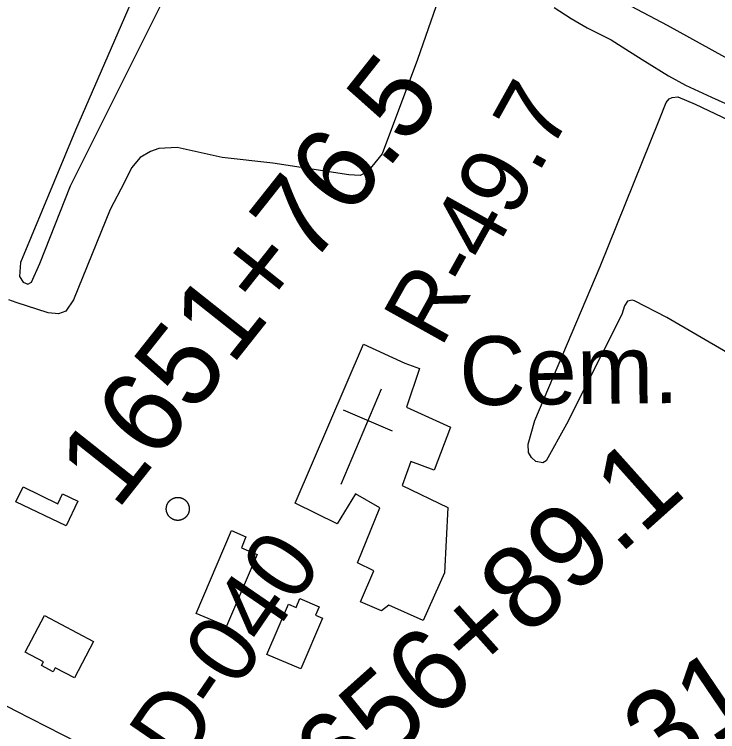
# Model space of a CAD drawing. Extents: x 3734862 to 3772949, y 391520 to 417239.
# Drawn here: x 3765922 to 3766771, y 398025 to 398891 of the extents above; entities that cross this region are included whole.
import ezdxf

# ---------------------------------------------------------------- set-up
doc = ezdxf.new("R2010")
doc.units = 0
for name, color, linetype in [('V-BLDG-IDEN', 7, 'Continuous'), ('V-BLDG-OTLN', 7, 'Continuous'), ('V-DOMW-TANK', 7, 'Continuous'), ('V-RIVR-EDGE', 7, 'Continuous'), ('V-RIVR-RANG-IDEN', 7, 'Continuous'), ('V-ROAD-CNTR', 7, 'Continuous'), ('V-SITE-OTLN', 7, 'Continuous'), ('V-SITE-VEGE', 7, 'Continuous'), ('V-SURV-IDEN', 7, 'Continuous'), ('V-TOPO-SHOR', 7, 'Continuous')]:
    doc.layers.add(name, color=color, linetype=linetype)

msp = doc.modelspace()

# ---------------------------------------------------------------- linework, layer by layer
at = {"layer": 'V-BLDG-OTLN'}
for points in [[(3765984.11, 398273.48), (3765923.61, 398302.47), (3765932.15, 398320.29), (3765974.36, 398300.06), (3765979.97, 398311.78), (3765998.26, 398303.01)], [(3766214.75, 398238.73), (3766178.08, 398152.14), (3766141.41, 398167.66), (3766183.75, 398267.61), (3766201.41, 398260.13), (3766195.8, 398246.75)], [(3766293.67, 398161.73), (3766267.64, 398100.65), (3766226.78, 398118.05), (3766252.6, 398178.65), (3766261.95, 398174.67), (3766266.6, 398185.57), (3766289.69, 398175.72), (3766285.26, 398165.31)], [(3765958.12, 398164.97), (3766017.44, 398133.6), (3765994.21, 398089.68), (3765970.89, 398102.02), (3765968.35, 398097.21), (3765954.39, 398104.59), (3765956.89, 398109.32), (3765934.86, 398120.97)]]:
    msp.add_lwpolyline(points, close=True, dxfattribs=at)
at = {"layer": 'V-DOMW-TANK'}
for points in [[(3766108.56, 398302.86), (3766108.72, 398303.04), (3766108.88, 398303.22), (3766109.05, 398303.4), (3766109.22, 398303.57), (3766109.39, 398303.74), (3766109.56, 398303.91), (3766109.74, 398304.07), (3766109.93, 398304.23), (3766110.11, 398304.39), (3766110.3, 398304.54), (3766110.48, 398304.7), (3766110.68, 398304.84), (3766110.87, 398304.99), (3766111.07, 398305.13), (3766111.27, 398305.26), (3766111.47, 398305.4), (3766111.67, 398305.53), (3766111.88, 398305.66), (3766112.09, 398305.78), (3766112.3, 398305.9), (3766112.51, 398306.01), (3766112.72, 398306.13), (3766112.94, 398306.23), (3766113.16, 398306.34), (3766113.38, 398306.44), (3766113.6, 398306.54), (3766113.83, 398306.63), (3766114.05, 398306.72), (3766114.28, 398306.8), (3766114.51, 398306.88), (3766114.74, 398306.96), (3766114.97, 398307.04), (3766115.2, 398307.11), (3766115.43, 398307.17), (3766115.67, 398307.23), (3766115.9, 398307.29), (3766116.14, 398307.34), (3766116.37, 398307.39), (3766116.61, 398307.43), (3766116.85, 398307.47), (3766117.09, 398307.51), (3766117.33, 398307.54), (3766117.57, 398307.57), (3766117.81, 398307.59), (3766118.05, 398307.61), (3766118.29, 398307.63), (3766118.54, 398307.64), (3766118.78, 398307.64), (3766119.02, 398307.65), (3766119.26, 398307.65), (3766119.5, 398307.64), (3766119.75, 398307.63), (3766119.99, 398307.62), (3766120.23, 398307.6), (3766120.47, 398307.57), (3766120.71, 398307.55), (3766120.95, 398307.51), (3766121.19, 398307.48), (3766121.43, 398307.44), (3766121.67, 398307.4), (3766121.91, 398307.35), (3766122.14, 398307.3), (3766122.38, 398307.24), (3766122.61, 398307.18), (3766122.85, 398307.12), (3766123.08, 398307.05), (3766123.31, 398306.98), (3766123.54, 398306.9), (3766123.77, 398306.82), (3766124, 398306.73), (3766124.22, 398306.65), (3766124.45, 398306.55), (3766124.67, 398306.46), (3766124.89, 398306.36), (3766125.11, 398306.25), (3766125.32, 398306.15), (3766125.54, 398306.03), (3766125.75, 398305.92), (3766125.96, 398305.8), (3766126.17, 398305.68), (3766126.38, 398305.55), (3766126.58, 398305.42), (3766126.78, 398305.29), (3766126.98, 398305.15), (3766127.18, 398305.01), (3766127.38, 398304.86), (3766127.57, 398304.72), (3766127.76, 398304.57), (3766127.95, 398304.42), (3766128.13, 398304.26), (3766128.31, 398304.1), (3766128.49, 398303.93), (3766128.67, 398303.77), (3766128.84, 398303.6), (3766129.01, 398303.42), (3766129.18, 398303.25), (3766129.34, 398303.07), (3766129.5, 398302.89), (3766129.66, 398302.71), (3766129.81, 398302.52)], [(3766111.92, 398281.87), (3766111.71, 398281.99), (3766111.51, 398282.12), (3766111.31, 398282.26), (3766111.1, 398282.39), (3766110.91, 398282.54), (3766110.71, 398282.68), (3766110.52, 398282.83), (3766110.33, 398282.98), (3766110.14, 398283.13), (3766109.96, 398283.29), (3766109.78, 398283.45), (3766109.6, 398283.61), (3766109.42, 398283.78), (3766109.25, 398283.95), (3766109.08, 398284.12), (3766108.91, 398284.29), (3766108.75, 398284.47), (3766108.59, 398284.65), (3766108.43, 398284.84), (3766108.28, 398285.02), (3766108.12, 398285.22), (3766107.98, 398285.41), (3766107.83, 398285.6), (3766107.69, 398285.8), (3766107.56, 398286), (3766107.42, 398286.2), (3766107.29, 398286.4), (3766107.16, 398286.61), (3766107.04, 398286.82), (3766106.92, 398287.03), (3766106.8, 398287.24), (3766106.69, 398287.46), (3766106.58, 398287.67), (3766106.48, 398287.89), (3766106.38, 398288.11), (3766106.28, 398288.33), (3766106.19, 398288.56), (3766106.1, 398288.78), (3766106.02, 398289.01), (3766105.93, 398289.24), (3766105.85, 398289.47), (3766105.78, 398289.7), (3766105.71, 398289.93), (3766105.65, 398290.16), (3766105.59, 398290.4), (3766105.53, 398290.63), (3766105.48, 398290.87), (3766105.43, 398291.1), (3766105.38, 398291.34), (3766105.34, 398291.58), (3766105.31, 398291.82), (3766105.28, 398292.06), (3766105.25, 398292.3), (3766105.23, 398292.54), (3766105.2, 398292.78), (3766105.19, 398293.03), (3766105.18, 398293.27), (3766105.17, 398293.51), (3766105.17, 398293.75), (3766105.17, 398293.99), (3766105.18, 398294.24), (3766105.19, 398294.48), (3766105.2, 398294.72), (3766105.22, 398294.96), (3766105.24, 398295.2), (3766105.27, 398295.44), (3766105.3, 398295.68), (3766105.34, 398295.92), (3766105.38, 398296.16), (3766105.42, 398296.4), (3766105.47, 398296.64), (3766105.52, 398296.87), (3766105.58, 398297.11), (3766105.64, 398297.35), (3766105.7, 398297.58), (3766105.77, 398297.81), (3766105.84, 398298.04), (3766105.92, 398298.27), (3766106, 398298.5), (3766106.08, 398298.73), (3766106.17, 398298.95), (3766106.26, 398299.18), (3766106.36, 398299.4), (3766106.46, 398299.62), (3766106.56, 398299.84), (3766106.67, 398300.05), (3766106.78, 398300.27), (3766106.9, 398300.48), (3766107.02, 398300.69), (3766107.14, 398300.9), (3766107.27, 398301.11), (3766107.4, 398301.31), (3766107.53, 398301.52), (3766107.67, 398301.72), (3766107.81, 398301.91), (3766107.95, 398302.11), (3766108.1, 398302.3), (3766108.25, 398302.49), (3766108.4, 398302.68), (3766108.56, 398302.86)], [(3766129.81, 398302.52), (3766129.96, 398302.33), (3766130.11, 398302.14), (3766130.26, 398301.94), (3766130.4, 398301.75), (3766130.54, 398301.55), (3766130.67, 398301.35), (3766130.8, 398301.14), (3766130.93, 398300.93), (3766131.05, 398300.73), (3766131.17, 398300.52), (3766131.29, 398300.3), (3766131.4, 398300.09), (3766131.51, 398299.87), (3766131.61, 398299.65), (3766131.71, 398299.43), (3766131.81, 398299.21), (3766131.9, 398298.99), (3766131.99, 398298.76), (3766132.08, 398298.54), (3766132.16, 398298.31), (3766132.24, 398298.08), (3766132.31, 398297.85), (3766132.38, 398297.61), (3766132.44, 398297.38), (3766132.5, 398297.15), (3766132.56, 398296.91), (3766132.61, 398296.67), (3766132.66, 398296.44), (3766132.71, 398296.2), (3766132.75, 398295.96), (3766132.78, 398295.72), (3766132.81, 398295.48), (3766132.84, 398295.24), (3766132.86, 398295), (3766132.89, 398294.76), (3766132.9, 398294.52), (3766132.91, 398294.27), (3766132.92, 398294.03), (3766132.92, 398293.79), (3766132.92, 398293.55), (3766132.91, 398293.31), (3766132.9, 398293.07), (3766132.89, 398292.82), (3766132.87, 398292.58), (3766132.85, 398292.34), (3766132.82, 398292.1), (3766132.79, 398291.86), (3766132.75, 398291.62), (3766132.71, 398291.38), (3766132.67, 398291.14), (3766132.62, 398290.91), (3766132.57, 398290.67), (3766132.51, 398290.43), (3766132.45, 398290.2), (3766132.39, 398289.97), (3766132.32, 398289.73), (3766132.25, 398289.5), (3766132.17, 398289.27), (3766132.09, 398289.04), (3766132.01, 398288.82), (3766131.92, 398288.59), (3766131.83, 398288.37), (3766131.73, 398288.15), (3766131.63, 398287.93), (3766131.52, 398287.71), (3766131.42, 398287.49), (3766131.31, 398287.28), (3766131.19, 398287.06), (3766131.07, 398286.85), (3766130.95, 398286.64), (3766130.83, 398286.43), (3766130.69, 398286.23), (3766130.56, 398286.03), (3766130.42, 398285.83), (3766130.28, 398285.63), (3766130.14, 398285.44), (3766129.99, 398285.24), (3766129.84, 398285.05), (3766129.69, 398284.87), (3766129.53, 398284.68), (3766129.37, 398284.5), (3766129.21, 398284.32), (3766129.04, 398284.15), (3766128.87, 398283.97), (3766128.7, 398283.8), (3766128.52, 398283.64), (3766128.35, 398283.47), (3766128.16, 398283.31), (3766127.98, 398283.15), (3766127.8, 398283), (3766127.6, 398282.85), (3766127.41, 398282.7), (3766127.22, 398282.56), (3766127.02, 398282.42), (3766126.82, 398282.28), (3766126.62, 398282.15), (3766126.42, 398282.02), (3766126.21, 398281.89), (3766126, 398281.77), (3766125.79, 398281.65)], [(3766125.79, 398281.65), (3766125.58, 398281.53), (3766125.37, 398281.42), (3766125.15, 398281.31), (3766124.93, 398281.21), (3766124.71, 398281.1), (3766124.49, 398281.01), (3766124.27, 398280.92), (3766124.04, 398280.82), (3766123.81, 398280.74), (3766123.58, 398280.66), (3766123.35, 398280.58), (3766123.12, 398280.51), (3766122.89, 398280.44), (3766122.66, 398280.37), (3766122.42, 398280.31), (3766122.19, 398280.26), (3766121.95, 398280.2), (3766121.71, 398280.15), (3766121.48, 398280.11), (3766121.24, 398280.07), (3766121, 398280.03), (3766120.76, 398280), (3766120.52, 398279.97), (3766120.28, 398279.95), (3766120.04, 398279.93), (3766119.79, 398279.92), (3766119.55, 398279.91), (3766119.31, 398279.9), (3766119.07, 398279.9), (3766118.83, 398279.9), (3766118.58, 398279.9), (3766118.34, 398279.91), (3766118.1, 398279.93), (3766117.86, 398279.95), (3766117.62, 398279.97), (3766117.38, 398280), (3766117.14, 398280.03), (3766116.9, 398280.06), (3766116.66, 398280.1), (3766116.42, 398280.15), (3766116.18, 398280.2), (3766115.95, 398280.25), (3766115.71, 398280.3), (3766115.48, 398280.36), (3766115.24, 398280.43), (3766115.01, 398280.5), (3766114.78, 398280.57), (3766114.55, 398280.65), (3766114.32, 398280.73), (3766114.1, 398280.81), (3766113.87, 398280.9), (3766113.64, 398280.99), (3766113.42, 398281.09), (3766113.2, 398281.19), (3766112.98, 398281.29), (3766112.77, 398281.4), (3766112.55, 398281.51), (3766112.34, 398281.63), (3766112.13, 398281.74), (3766111.92, 398281.87)]]:
    msp.add_lwpolyline(points, dxfattribs=at)
at = {"layer": 'V-RIVR-EDGE'}
msp.add_spline([(3755702.08, 404495.32), (3755757.18, 404470.77), (3755793.3, 404451.23), (3755852.47, 404424.41), (3755881.39, 404415.75), (3755906.23, 404404.38), (3755920.22, 404395.76), (3755948.67, 404379.41), (3755958.16, 404378.93), (3755969.01, 404378), (3755990.69, 404368.45), (3756022.75, 404350.29), (3756054.82, 404336.64), (3756079.66, 404323.02), (3756103.59, 404309.39), (3756144.23, 404288.04), (3756167.69, 404268.99), (3756188.91, 404253.57), (3756231.36, 404233.11), (3756271.56, 404217.19), (3756299.11, 404203.1), (3756403.01, 404163.51), (3756460.37, 404140.31), (3756508.69, 404114.87), (3756530.82, 404103.96), (3756588.18, 404078.04), (3756639.21, 404052.15), (3756694.29, 404019.45), (3756726.8, 403998.12), (3756735.82, 403989.06), (3756740.32, 403979.55), (3756740.3, 403973.22), (3756740.74, 403967.79), (3756747.5, 403960.54), (3756759.69, 403953.73), (3756786.34, 403941.46), (3756814.34, 403929.18), (3756864.47, 403904.64), (3756889.32, 403895.98), (3756899.72, 403897.32), (3756908.33, 403901.82), (3756919.18, 403901.34), (3756933.18, 403894.07), (3756945.83, 403892.68), (3756956.23, 403893.11), (3756962.12, 403897.16), (3756970.71, 403896.69), (3756978.39, 403894.41), (3756992.41, 403894.83), (3757002.82, 403897.51), (3757019.1, 403901.54), (3757027.7, 403901.52), (3757034.02, 403901.05), (3757036.27, 403896.53), (3757036.71, 403891.1), (3757038.5, 403883.41), (3757046.62, 403874.34), (3757060.62, 403866.17), (3757076.41, 403853.92), (3757104.39, 403831.25), (3757122.44, 403816.73), (3757145.47, 403804.47), (3757165.34, 403796.73), (3757181.6, 403787.2), (3757194.24, 403777.67), (3757213.65, 403765.41), (3757229.9, 403756.33), (3757251.58, 403745.88), (3757266.49, 403741.32), (3757283.2, 403734.49), (3757308.94, 403720.87), (3757360.42, 403694.06), (3757393.83, 403670.92), (3757429.96, 403657.26), (3757461.59, 403645.43), (3757505.4, 403628.14), (3757548.31, 403610.4), (3757591.66, 403587.23), (3757649.45, 403552.27), (3757711.75, 403512.78), (3757753.76, 403493.23), (3757766.86, 403487.78), (3757773.19, 403487.76), (3757785.86, 403494.06), (3757794.45, 403494.04), (3757803.49, 403489.49), (3757807.08, 403480.89), (3757810.64, 403456.02), (3757814.23, 403447.87), (3757826.42, 403436.99), (3757854.41, 403422.9), (3757930.26, 403373.88), (3757975.85, 403342.57), (3758005.19, 403323.5), (3758062.07, 403286.74), (3758092.31, 403263.6), (3758175.82, 403209.59), (3758234.51, 403169.2), (3758283.7, 403133.81), (3758328.84, 403103.41), (3758399.23, 403041.74), (3758421.79, 403023.15), (3758438.05, 403017.68), (3758463.83, 403017.62), (3758491.43, 403026.14), (3758504.53, 403022.04), (3758513.56, 403014.33), (3758513.99, 403006.19), (3758499.95, 402997.18), (3758498.12, 402989.95), (3758502.16, 402978.18), (3758510.73, 402969.57), (3758522.02, 402962.76), (3758545.05, 402948.69), (3758582.07, 402926.89), (3758650.23, 402878.79), (3758697.61, 402840.7), (3758721.52, 402820.29), (3758740.94, 402809.39), (3758782.02, 402784.87), (3758831.24, 402755.36), (3758902.12, 402711.78), (3758960.36, 402675.46), (3759018.58, 402634.62), (3759069.59, 402599.68), (3759134.59, 402553.4), (3759185.57, 402508.06), (3759223.48, 402478.12), (3759262.29, 402448.18), (3759321.41, 402402.37), (3759371.51, 402366.07), (3759431.54, 402323.42), (3759463.59, 402300.28), (3759488.86, 402281.68), (3759576.89, 402222.68), (3759626.99, 402186.84), (3759672.12, 402153.72), (3759778.21, 402087.44), (3759832.83, 402050.68), (3759873, 402019.38), (3759909.55, 401989.45), (3760050.81, 401883.75), (3760100.02, 401850.16), (3760145.61, 401819.31), (3760185.77, 401788.01), (3760211.95, 401766.69), (3760254.82, 401734.48), (3760285.51, 401709.08), (3760303.12, 401700.45), (3760325.25, 401691.35), (3760352.78, 401671.39), (3760391.14, 401641), (3760430.41, 401611.96), (3760461.55, 401590.18), (3760536.95, 401542.97), (3760582.99, 401510.76), (3760602.85, 401495.79), (3760629.02, 401477.18), (3760672.36, 401449.49), (3760711.19, 401426.79), (3760818.61, 401347.85), (3760872.33, 401310.64), (3760925.58, 401271.62), (3760948.6, 401251.67), (3761039.76, 401181.81), (3761107.02, 401135.52), (3761151.7, 401104.67), (3761172.93, 401093.31), (3761186.03, 401090.57), (3761199.15, 401092.79), (3761219.51, 401099.07), (3761228.11, 401099.5), (3761233.52, 401095.42), (3761236.67, 401087.73), (3761236.64, 401077.78), (3761228.47, 401063.78), (3761223.03, 401057.47), (3761223.01, 401049.33), (3761228.86, 401039.37), (3761242.39, 401026.67), (3761254.14, 401021.67), (3761266.79, 401018.47), (3761292.52, 401001.68), (3761317.34, 400980.37), (3761342.15, 400955.44), (3761463.07, 400853.4), (3761509.99, 400812.14), (3761550.15, 400777.68), (3761585.34, 400746.84), (3761681.47, 400674.26), (3761756.4, 400618.91), (3761817.77, 400572.19), (3761878.26, 400530.44), (3761996.49, 400436.55), (3762057.42, 400389.83), (3762104.8, 400352.63), (3762156.25, 400313.17), (3762204.54, 400277.33), (3762245.17, 400247.84), (3762291.65, 400210.19), (3762325.94, 400182.07), (3762356.18, 400159.84), (3762404.02, 400123.55), (3762432.9, 400101.32), (3762455.49, 400091.32), (3762473.53, 400075.9), (3762512.34, 400044.16), (3762551.6, 400012.41), (3762593.58, 399983.82), (3762620.21, 399963.4), (3762661.74, 399937.08), (3762686.57, 399919.83), (3762793.08, 399841.35), (3762834.61, 399812.76), (3762873.44, 399790.05), (3762923.1, 399758.28), (3762956.96, 399737.4), (3762984.05, 399721.5), (3763024.22, 399693.37), (3763075.23, 399657.52), (3763115.86, 399633.91), (3763172.75, 399601.21), (3763228.74, 399568.52), (3763285.17, 399533.57), (3763344.31, 399494.08), (3763398.47, 399455.06), (3763444.06, 399421.04), (3763484.68, 399391.09), (3763603.38, 399303.08), (3763654.82, 399261.81), (3763661.14, 399259.53), (3763667.01, 399254.54), (3763671.96, 399245.04), (3763696.33, 399224.18), (3763722.94, 399200.15), (3763745.5, 399180.2), (3763818.14, 399117.17), (3763841.61, 399099.47), (3763852.45, 399092.21), (3763858.76, 399084.06), (3763874.99, 399067.29), (3763898, 399045.98), (3763924.62, 399023.76), (3763949, 399007.87), (3763970.2, 398987.47), (3764004.03, 398952.57), (3764028.38, 398926.74), (3764056.8, 398899.54), (3764092.88, 398862.37), (3764130.77, 398826.11), (3764147.01, 398811.6), (3764152.86, 398799.83), (3764162.32, 398783.53), (3764173.58, 398768.58), (3764186.67, 398757.24), (3764206.08, 398746.34), (3764226.87, 398742.22), (3764246.29, 398733.58), (3764269.32, 398717.7), (3764284.2, 398703.19), (3764301.81, 398691.84), (3764323.02, 398678.23), (3764345.14, 398660.99), (3764412.35, 398596.62), (3764457.02, 398559.88), (3764502.6, 398522.69), (3764538.26, 398497.74), (3764566.26, 398486.36), (3764583.89, 398484.51), (3764604.25, 398486.27), (3764616.45, 398486.24), (3764626.39, 398481.69), (3764630.89, 398474.45), (3764636.29, 398461.32), (3764634.9, 398450.02), (3764631.72, 398441.44), (3764633.06, 398434.65), (3764636.21, 398430.12), (3764643.89, 398425.58), (3764661.06, 398421.47), (3764685.44, 398409.2), (3764715.22, 398382), (3764745.45, 398356.15), (3764793.31, 398328), (3764844.31, 398292.6), (3764885.83, 398258.14), (3764918.78, 398234.54), (3764992.82, 398187.79), (3765058.27, 398144.22), (3765088.07, 398128.32), (3765140.91, 398100.15), (3765168.89, 398079.74), (3765193.71, 398061.59), (3765246.12, 398042.02), (3765282.23, 398018.42), (3765309.74, 397989.41), (3765339.95, 397955.42), (3765361.15, 397933.67), (3765382.35, 397911.91), (3765434.69, 397867.92), (3765477.57, 397838.43), (3765508.73, 397823.88), (3765545.3, 397801.18), (3765575.54, 397778.05), (3765617.52, 397749.91), (3765653.64, 397726.31), (3765681.63, 397709.96), (3765727.23, 397684.53), (3765761.99, 397660.02), (3765771.94, 397659.55), (3765788.21, 397659.96), (3765793.64, 397658.14), (3765793.63, 397653.62), (3765785.47, 397648.66), (3765785.47, 397645.5), (3765790.86, 397632.82), (3765800.33, 397623.76), (3765814.78, 397612.87), (3765831.94, 397605.59), (3765847.31, 397603.29), (3765858.15, 397598.75), (3765865.82, 397593.3), (3765888.84, 397576.97), (3765908.7, 397561.54), (3765918.16, 397548.41), (3765919.5, 397542.07), (3765921.3, 397536.19), (3765926.71, 397533.46), (3765933.05, 397534.35), (3765940.73, 397533.43), (3765944.79, 397530.25), (3765956.97, 397519.37), (3765987.67, 397499.85), (3766024.67, 397468.11), (3766059.41, 397438.18), (3766085.13, 397413.25), (3766102.73, 397400.09), (3766131.61, 397377.42), (3766172.69, 397350.18), (3766210.59, 397318.89), (3766264.32, 397285.3), (3766306.76, 397260.78), (3766362.73, 397220.85), (3766381.12, 397208.5)], degree=3, dxfattribs=at)
at = {"layer": 'V-ROAD-CNTR'}
msp.add_lwpolyline([(3764722.94, 398724.48), (3764774.26, 398695.49), (3764825.72, 398666.73), (3764877.38, 398638.16), (3765048.14, 398542.14), (3765204.25, 398453.13), (3765349.06, 398368.89), (3765503.3, 398282.87), (3765646.99, 398199.77), (3765779.29, 398126.18), (3765922.48, 398050.51), (3766092.78, 397963.66)], dxfattribs=at)
at = {"layer": 'V-SITE-OTLN'}
for p, q in [((3766316.42, 398323.75), (3766365.1, 398438.6)), ((3766378.54, 398387.75), (3766319.2, 398412.9))]:
    msp.add_line(p, q, dxfattribs=at)
msp.add_lwpolyline([(3766441.13, 398216.54), (3766415.38, 398159.12), (3766373.76, 398177.57), (3766364.91, 398170.63), (3766339.86, 398181.39), (3766356, 398219.15), (3766335.97, 398228.76), (3766362.87, 398295.04), (3766333.58, 398311.96), (3766311.66, 398275.73), (3766260.79, 398300.71), (3766343.42, 398492.61), (3766393.13, 398469.55), (3766410.85, 398463.4), (3766395.1, 398416.78), (3766448.28, 398392.57), (3766428.69, 398340.55), (3766400.56, 398350.92), (3766390.19, 398322.02), (3766445.29, 398295.5)], close=True, dxfattribs=at)
at = {"layer": 'V-SITE-VEGE'}
for points in [[(3766085.89, 398958.78), (3765995.39, 398751.2), (3765929.14, 398591.07), (3765927.97, 398574.47), (3765932.13, 398567.36), (3765938.06, 398565), (3765942.21, 398567.37), (3765952.27, 398589.91), (3765989.52, 398683.61), (3766061.12, 398827.15), (3766123.84, 398952.89)], [(3766443.39, 398937.18), (3766408.51, 398836.37), (3766365.94, 398722.51), (3766348.17, 398700.55), (3766339.28, 398696.4), (3766325.65, 398696.98), (3766233.75, 398711.12), (3766172.68, 398718.17), (3766118.12, 398729.98), (3766096.19, 398728.77), (3766086.12, 398725.2), (3766073.67, 398718.08), (3766063.02, 398705.62), (3766054.73, 398688.42), (3766037.57, 398655.2), (3765993.21, 398546.08), (3765983.74, 398532.43), (3765974.85, 398529.46), (3765962.4, 398530.64), (3765923.85, 398543.05), (3765914.96, 398546.01)], [(3766819.47, 398461.03), (3766709.73, 398524.95), (3766670.58, 398545.07), (3766667.62, 398545.66), (3766662.29, 398544.47), (3766658.73, 398539.13), (3766655.19, 398528.45), (3766588.32, 398396.18), (3766564.06, 398351.7), (3766559.91, 398349.33), (3766551.61, 398351.1), (3766546.27, 398355.83), (3766542.71, 398361.76), (3766542.1, 398371.84), (3766550.38, 398400.3), (3766629.05, 398586.53), (3766700.61, 398763.26), (3766708.89, 398784.6), (3766712.44, 398788.76), (3766716, 398790.54), (3766723.11, 398791.14), (3766743.87, 398782.27), (3766880.28, 398717.78)]]:
    msp.add_lwpolyline(points, dxfattribs=at)
at = {"layer": 'V-TOPO-SHOR'}
for points in [[(3766622.39, 398924.57), (3766709.94, 398877.67), (3766791.04, 398833.11)], [(3766573.66, 398899.27), (3766594.23, 398885.78), (3766613.62, 398874.64), (3766642.42, 398859.99), (3766664.75, 398845.91), (3766682.97, 398834.18), (3766711.76, 398816.59), (3766732.33, 398805.45), (3766763.47, 398790.8), (3766792.27, 398777.9)]]:
    msp.add_lwpolyline(points, dxfattribs=at)

# ---------------------------------------------------------------- texts
at = {"layer": 'V-BLDG-IDEN'}
msp.add_text('Cem.', height=83, rotation=0.6, dxfattribs=at).set_placement((3766459.42, 398418.82))
at = {"layer": 'V-RIVR-RANG-IDEN'}
for s, rotation, p in [('R-49.7', 60.85574, (3766436.7, 398486.71)), ('D-040', 55.60533, (3766124.3, 397978.87))]:
    msp.add_text(s, height=83, rotation=rotation, dxfattribs=at).set_placement(p)
at = {"layer": 'V-SURV-IDEN'}
for s, rotation, p in [('1651+76.5', 51.5883, (3766045.51, 398290.72)), ('1656+89.1', 41.7907, (3766260.62, 397887.55)), ('1656+31.4', 34.1188, (3766391.8, 397754.03))]:
    msp.add_text(s, height=100, rotation=rotation, dxfattribs=at).set_placement(p)

doc.saveas('drawing.dxf')
